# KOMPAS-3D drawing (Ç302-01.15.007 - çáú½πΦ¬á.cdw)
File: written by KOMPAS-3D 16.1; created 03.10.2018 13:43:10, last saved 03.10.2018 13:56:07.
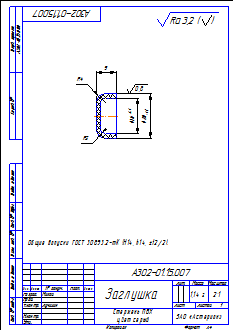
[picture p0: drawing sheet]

Sheet 1: A4, portrait

Title block, sheet 1: name: Заглушка; designation: А302-01.15.007; mass: 1,14 г; scale: 2:1; sheets: 1; organisation: ЗАО «Астерион»; sheet format: A4; stored path: \\192.168.87.28\Konstructor_doc\Мембранные насосы\Мембранный электропривод\А302-00.00.000 - ASTRA-302 (МЭ200)\3Д ПВХ\А302-01.15.007 - Заглушка.cdw; drawn by: Милов; technical control: Лучихин

Views: Вид 1, Местный разрез 1, Спереди, Проекционный вид 2
Referenced files in Z:\Мембранные насосы\Мембранный электропривод\А302-00.00.000 - ASTRA-302 (МЭ200)\3Д ПВХ\: А302-01.15.007 - Заглушка.m3d
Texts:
  Стержень ПВХ
  цвет серый
  Общие допуски ГОСТ 30893.2-mK (H14, h14,  t2/2).
  Ra 3,2
  Ra 3,2 ( )
Dimensions and other numbers on the sheet: 9; 16; 20; 0,8; 2; 4; 2:1; 1; 1,14 г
